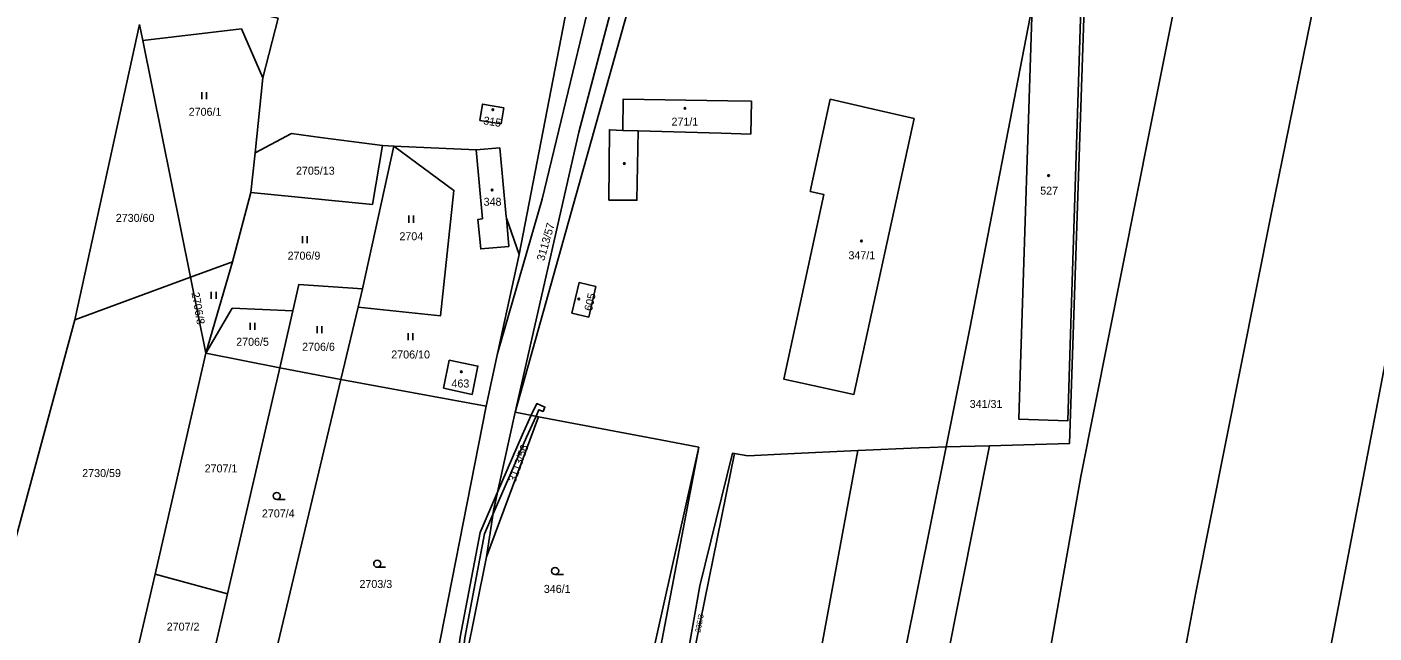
# Model space of a CAD drawing. Extents: x -776734 to -748832, y -1118122 to -976986.
# Drawn here: x -753561.2 to -753275.1, y -1115314.3 to -1115185.5 of the extents above; entities that cross this region are included whole.
import ezdxf

# ---------------------------------------------------------------- set-up
doc = ezdxf.new("R2010")
doc.units = 0
for name, color, linetype in [('KM_Hranice parcel', 7, 'Continuous'), ('KM_Parcelní čísla', 7, 'Continuous'), ('KM_Vnitřní kresba', 7, 'Continuous'), ('KM_Věcná břemena k části', 7, 'Continuous'), ('KM_Značky budov', 7, 'Continuous'), ('KM_Značky kultur', 7, 'Continuous')]:
    doc.layers.add(name, color=color, linetype=linetype)

msp = doc.modelspace()

# ---------------------------------------------------------------- linework, layer by layer
at = {"layer": 'KM_Hranice parcel'}
for p, q in [((-753551.09, -1115247.71), (-753537.32, -1115185.01)), ((-753537.32, -1115185.01), (-753536.64, -1115188.38)), ((-753536.64, -1115188.38), (-753526.49, -1115238.66)), ((-753511.13, -1115196.3), (-753512.8, -1115212.26)), ((-753460.55, -1115206.1), (-753459.98, -1115202.67)), ((-753513.68, -1115220.64), (-753512.8, -1115212.26)), ((-753483.34, -1115210.8), (-753489.96, -1115241.16)), ((-753485.75, -1115210.69), (-753483.34, -1115210.8)), ((-753483.34, -1115210.8), (-753465.82, -1115211.6)), ((-753460.79, -1115211.21), (-753465.82, -1115211.6)), ((-753464.49, -1115226.28), (-753465.82, -1115211.6)), ((-753459.46, -1115225.83), (-753460.79, -1115211.21)), ((-753517.56, -1115235.38), (-753513.68, -1115220.64)), ((-753459.42, -1115226.15), (-753459.46, -1115225.83)), ((-753459.42, -1115226.15), (-753458.87, -1115232.11)), ((-753459.42, -1115226.15), (-753456.72, -1115233.86)), ((-753526.49, -1115238.66), (-753517.56, -1115235.38)), ((-753523.22, -1115254.83), (-753517.56, -1115235.38)), ((-753461.28, -1115254.86), (-753456.72, -1115233.86)), ((-753526.49, -1115238.66), (-753551.09, -1115247.71)), ((-753526.49, -1115238.66), (-753523.22, -1115254.83)), ((-753489.96, -1115241.16), (-753490.89, -1115245.05)), ((-753567.23, -1115307.22), (-753551.09, -1115247.71)), ((-753517.65, -1115245.24), (-753523.22, -1115254.83)), ((-753504.77, -1115245.83), (-753517.65, -1115245.24)), ((-753507.56, -1115257.91), (-753504.77, -1115245.83)), ((-753494.55, -1115260.42), (-753490.89, -1115245.05)), ((-753523.22, -1115254.83), (-753534.03, -1115301.72)), ((-753523.22, -1115254.83), (-753507.56, -1115257.91)), ((-753463.72, -1115266.09), (-753461.28, -1115254.86)), ((-753518.64, -1115305.9), (-753507.56, -1115257.91)), ((-753507.56, -1115257.91), (-753494.55, -1115260.42)), ((-753494.55, -1115260.42), (-753509.14, -1115321.59)), ((-753494.55, -1115260.42), (-753463.72, -1115266.09)), ((-753457.55, -1115267.36), (-753452.57, -1115268.3)), ((-753452.57, -1115268.3), (-753463.62, -1115298.06)), ((-753452.57, -1115268.3), (-753426.68, -1115273.2)), ((-753426.68, -1115273.2), (-753418.54, -1115274.74)), ((-753418.54, -1115274.74), (-753433.23, -1115340.67)), ((-753410.93, -1115276.14), (-753424.75, -1115344.05)), ((-753401.71, -1115367.14), (-753384.76, -1115275.5)), ((-753399.74, -1115276.21), (-753384.76, -1115275.5)), ((-753377.86, -1115380.06), (-753356.82, -1115274.48)), ((-753356.82, -1115274.48), (-753365.98, -1115274.73)), ((-753534.03, -1115301.72), (-753537.81, -1115318.08)), ((-753534.03, -1115301.72), (-753518.64, -1115305.9)), ((-753521.68, -1115319.09), (-753518.64, -1115305.9))]:
    msp.add_line(p, q, dxfattribs=at)
for points in [[(-753337.09, -1115412.19), (-753331.62, -1115395.18), (-753319.53, -1115340.8), (-753312.98, -1115305.64), (-753296.9, -1115224.92), (-753280.25, -1115143.21), (-753266.59, -1115079.29), (-753255.81, -1115019.21), (-753246.42, -1114978.13)], [(-753308.1, -1115421.53), (-753299.05, -1115385.38), (-753292.72, -1115360.89), (-753274.02, -1115263.55), (-753259.94, -1115189.91), (-753242.27, -1115107.78), (-753230.26, -1115041.93), (-753222.65, -1115005.26), (-753215.61, -1114976.64)], [(-753276.79, -1114979.6), (-753284.56, -1115013.08), (-753289.35, -1115035.78), (-753298.04, -1115085.94), (-753309.52, -1115141.15), (-753322.69, -1115207.01), (-753337.4, -1115280.99), (-753345.39, -1115326.25), (-753352.25, -1115356.38), (-753360.84, -1115388.75), (-753362.55, -1115393.05)], [(-753365.98, -1115274.73), (-753361.01, -1115249.56), (-753347.77, -1115181.15), (-753334.54, -1115118.07)], [(-753356.82, -1115274.48), (-753339.82, -1115274.01), (-753336.33, -1115170.94), (-753334.54, -1115118.07)], [(-753422.22, -1115156.3), (-753428.4, -1115163.22), (-753457.55, -1115267.36)], [(-753457.55, -1115267.36), (-753444.06, -1115207.85), (-753433.78, -1115168.87), (-753432, -1115158.56)], [(-753438.02, -1115162.52), (-753441.76, -1115180.46), (-753451.82, -1115222.08), (-753461.28, -1115254.86)], [(-753456.72, -1115233.86), (-753446.92, -1115183.35), (-753440.99, -1115164.47), (-753438.02, -1115162.52)], [(-753535.73, -1115177.62), (-753507.87, -1115183.65), (-753511.13, -1115196.3)], [(-753339.84, -1115257.51), (-753337.42, -1115181.48), (-753347.77, -1115181.15), (-753350.19, -1115257.18), (-753350.56, -1115268.83), (-753340.19, -1115269.2), (-753339.84, -1115257.51)], [(-753511.13, -1115196.3), (-753515.65, -1115185.92), (-753536.64, -1115188.38)], [(-753459.98, -1115202.67), (-753464.48, -1115201.87), (-753465.05, -1115205.35), (-753460.55, -1115206.1)], [(-753407.38, -1115201.29), (-753407.5, -1115208.27), (-753413.81, -1115208.09), (-753431.44, -1115207.59), (-753431.7, -1115222.3), (-753437.62, -1115222.26), (-753437.52, -1115207.33), (-753434.7, -1115207.5), (-753434.58, -1115200.82), (-753412.39, -1115201.2), (-753407.38, -1115201.29)], [(-753394.9, -1115220.47), (-753391.97, -1115221.11), (-753400.45, -1115260.34), (-753394.3, -1115261.67), (-753385.6, -1115263.55), (-753372.82, -1115204.95), (-753381.78, -1115202.88), (-753390.63, -1115200.84), (-753394.9, -1115220.47)], [(-753512.8, -1115212.26), (-753505.07, -1115208.11), (-753498.89, -1115208.98), (-753485.75, -1115210.69)], [(-753513.68, -1115220.64), (-753487.86, -1115223.19), (-753485.75, -1115210.69)], [(-753490.89, -1115245.05), (-753473.44, -1115246.9), (-753470.54, -1115220.24), (-753483.34, -1115210.8)], [(-753458.87, -1115232.11), (-753464.87, -1115232.66), (-753465.47, -1115226.37), (-753464.49, -1115226.28)], [(-753504.77, -1115245.83), (-753503.47, -1115240.18), (-753489.96, -1115241.16)], [(-753441.93, -1115247.13), (-753445.5, -1115246.3), (-753443.97, -1115239.82), (-753440.4, -1115240.66), (-753441.93, -1115247.13)], [(-753472.77, -1115262.26), (-753466.65, -1115263.57), (-753465.45, -1115257.53), (-753471.56, -1115256.32), (-753472.77, -1115262.26)], [(-753478.97, -1115347.96), (-753475.82, -1115327.7), (-753463.72, -1115266.09)], [(-753457.55, -1115267.36), (-753462.08, -1115287.9), (-753463.62, -1115298.06)], [(-753418.54, -1115274.74), (-753429.97, -1115334.45), (-753435.62, -1115360.74)], [(-753410.93, -1115276.14), (-753411.42, -1115276.06), (-753418.3, -1115304.23)], [(-753410.93, -1115276.14), (-753408.11, -1115276.61), (-753399.74, -1115276.21)], [(-753388.04, -1115373.9), (-753377.88, -1115333.93), (-753365.98, -1115274.73)], [(-753365.98, -1115274.73), (-753369.45, -1115274.82), (-753371.8, -1115274.88), (-753384.76, -1115275.5)], [(-753477.94, -1115371.21), (-753474.76, -1115353.37), (-753470.21, -1115330.79), (-753463.62, -1115298.06)], [(-753418.3, -1115304.23), (-753423.5, -1115333.55), (-753424.75, -1115344.05)]]:
    msp.add_lwpolyline(points, dxfattribs=at)
at = {"layer": 'KM_Vnitřní kresba'}
msp.add_line((-753434.7, -1115207.5), (-753431.44, -1115207.59), dxfattribs=at)
at = {"layer": 'KM_Věcná břemena k části'}
for points in [[(-753455.16, -1115272.63), (-753453.12, -1115268.2), (-753452.49, -1115266.82), (-753451.62, -1115267.17), (-753451.23, -1115266.24), (-753452.98, -1115265.5), (-753454.13, -1115268), (-753456.08, -1115272.23), (-753461.29, -1115284.3), (-753462.26, -1115289.08)], [(-753462.08, -1115287.9), (-753461.29, -1115284.3), (-753465, -1115292.91), (-753469.22, -1115315.13), (-753472.33, -1115341.3), (-753470.21, -1115330.79), (-753469.83, -1115328.89), (-753468.23, -1115315.26), (-753464.04, -1115293.21), (-753462.26, -1115289.08)]]:
    msp.add_lwpolyline(points, close=True, dxfattribs=at)
at = {"layer": 'KM_Značky budov'}
for centre in [(-753462.2768, -1115203.0792), (-753421.4668, -1115202.7792), (-753434.3468, -1115214.5092), (-753344.2668, -1115217.0592), (-753462.4368, -1115220.1192), (-753383.9968, -1115230.9592), (-753444.0368, -1115243.2992), (-753468.9768, -1115258.7492)]:
    msp.add_circle(centre, 0.175, dxfattribs=at)
at = {"layer": 'KM_Značky kultur'}
for p, q in [((-753524.091, -1115200.82), (-753524.091, -1115199.32)), ((-753523.09, -1115200.82), (-753523.09, -1115199.32)), ((-753480.161, -1115227.08), (-753480.161, -1115225.58)), ((-753479.16, -1115227.08), (-753479.16, -1115225.58)), ((-753502.711, -1115231.46), (-753502.711, -1115229.96)), ((-753501.71, -1115231.46), (-753501.71, -1115229.96)), ((-753522.081, -1115243.25), (-753522.081, -1115241.75)), ((-753521.08, -1115243.25), (-753521.08, -1115241.75)), ((-753513.831, -1115249.85), (-753513.831, -1115248.35)), ((-753512.83, -1115249.85), (-753512.83, -1115248.35)), ((-753499.581, -1115250.58), (-753499.581, -1115249.08)), ((-753498.58, -1115250.58), (-753498.58, -1115249.08)), ((-753480.251, -1115252.03), (-753480.251, -1115250.53)), ((-753479.25, -1115252.03), (-753479.25, -1115250.53)), ((-753508.183, -1115285.88), (-753506.433, -1115285.88)), ((-753486.843, -1115300.29), (-753485.093, -1115300.29)), ((-753449.053, -1115301.83), (-753447.303, -1115301.83))]:
    msp.add_line(p, q, dxfattribs=at)
for centre in [(-753508.1829, -1115285.1298), (-753486.8429, -1115299.5398), (-753449.0529, -1115301.0798)]:
    msp.add_circle(centre, 0.75, dxfattribs=at)

# ---------------------------------------------------------------- texts
at = {"layer": 'KM_Parcelní čísla'}
for s, p in [('2706/1', (-753526.89, -1115204.37)), ('271/1', (-753424.34, -1115206.46)), ('2705/13', (-753504.1, -1115216.88)), ('348', (-753464.25, -1115223.48)), ('527', (-753346.03, -1115221.12)), ('2730/60', (-753542.37, -1115226.91)), ('2704', (-753482.13, -1115230.81)), ('2706/9', (-753505.88, -1115234.93)), ('347/1', (-753386.76, -1115234.85)), ('2706/5', (-753516.8, -1115253.23)), ('2706/6', (-753502.79, -1115254.29)), ('2706/10', (-753483.86, -1115255.93)), ('463', (-753471.08, -1115262.09)), ('341/31', (-753361.01, -1115266.44)), ('2707/1', (-753523.5, -1115280.13)), ('2730/59', (-753549.5, -1115281.12)), ('2707/4', (-753511.34, -1115289.7)), ('2703/3', (-753490.62, -1115304.69)), ('346/1', (-753451.46, -1115305.73)), ('2707/2', (-753531.55, -1115313.75))]:
    msp.add_text(s, height=1.7, dxfattribs=at).set_placement(p)
for s, height, rotation, p in [('315', 1.7, 351, (-753464.402, -1115206.159)), ('3113/57', 1.7, 74, (-753451.392, -1115235.314)), ('2706/8', 1.7, 280, (-753526.297, -1115241.987)), ('605', 1.7, 77, (-753441.261, -1115245.971)), ('3113/56', 1.7, 70, (-753457.491, -1115282.35)), ('235/3', 1.14, 79, (-753418.232, -1115314.23))]:
    msp.add_text(s, height=height, rotation=rotation, dxfattribs=at).set_placement(p)

doc.saveas('drawing.dxf')
